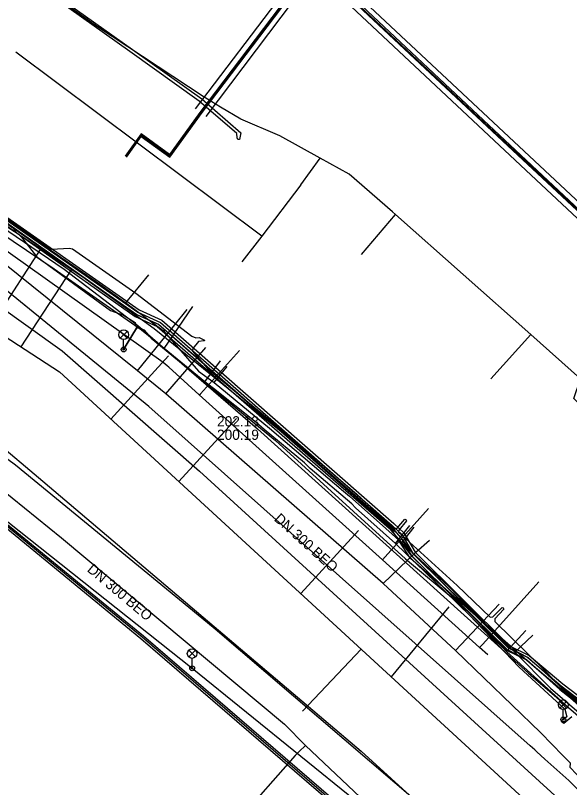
# Model space of a CAD drawing. Extents: x -598932 to -598196, y -1162210 to -1161504.
# Drawn here: x -598866.4 to -598823.1, y -1161758.8 to -1161698.4 of the extents above; entities that cross this region are included whole.
import ezdxf

# ---------------------------------------------------------------- set-up
doc = ezdxf.new("R2010")
doc.units = 0
for name, color, linetype in [('Vrstva 1', 7, 'Continuous'), ('Vrstva 12', 7, 'Continuous'), ('Vrstva 13', 7, 'Continuous'), ('Vrstva 14', 7, 'Continuous'), ('Vrstva 16', 7, 'Continuous'), ('Vrstva 19', 7, 'Continuous'), ('Vrstva 25', 7, 'Continuous'), ('Vrstva 26', 7, 'Continuous'), ('Vrstva 30', 7, 'Continuous'), ('Vrstva 33', 7, 'Continuous'), ('Vrstva 4', 7, 'Continuous'), ('Vrstva 42', 7, 'Continuous'), ('Vrstva 44', 7, 'Continuous'), ('Vrstva 55', 7, 'Continuous'), ('Vrstva 58', 7, 'Continuous'), ('Vrstva 9', 7, 'Continuous')]:
    doc.layers.add(name, color=color, linetype=linetype)

msp = doc.modelspace()

# ---------------------------------------------------------------- linework, layer by layer
at = {"layer": 'Vrstva 1'}
for p, q in [((-598892.23, -1161711.3), (-598864.64, -1161734.54)), ((-598864.64, -1161734.54), (-598839.42, -1161755.92)), ((-598852.066, -1161734.061), (-598815.57, -1161767.334)), ((-598839.42, -1161755.92), (-598800.999, -1161790.997))]:
    msp.add_line(p, q, dxfattribs=at)
msp.add_lwpolyline([(-598893.601, -1161702.614), (-598862.803, -1161724.661), (-598852.066, -1161734.061)], dxfattribs=at)
at = {"layer": 'Vrstva 12'}
for p, q in [((-598857.82, -1161720.91), (-598856.01, -1161718.71)), ((-598850.92, -1161727.13), (-598849.9, -1161725.86)), ((-598836.26, -1161739.64), (-598835.3, -1161738.43)), ((-598827.43, -1161748.2), (-598826.02, -1161746.86))]:
    msp.add_line(p, q, dxfattribs=at)
for points in [[(-598886.1, -1161699.15), (-598877.79, -1161704.85), (-598875.68, -1161706.42), (-598875.36, -1161706.84), (-598872.64, -1161710.75), (-598871.85, -1161711.4), (-598865.87, -1161715.26), (-598859.85, -1161719.44), (-598857.82, -1161720.91)], [(-598857.82, -1161720.91), (-598854.89, -1161723.07), (-598852.13, -1161726.23), (-598850.92, -1161727.13)], [(-598850.92, -1161727.13), (-598846.58, -1161730.68), (-598840.81, -1161735.6), (-598840.34, -1161736.01)], [(-598840.34, -1161736.01), (-598837.51, -1161738.54), (-598836.26, -1161739.64)], [(-598836.26, -1161739.64), (-598832.61, -1161743.04), (-598829.07, -1161746.62), (-598827.43, -1161748.2)], [(-598827.43, -1161748.2), (-598824.64, -1161751), (-598821.47, -1161753.73), (-598817.61, -1161756.73), (-598815.83, -1161758.13), (-598815.16, -1161758.58), (-598814.14, -1161758.66), (-598813.17, -1161758.37), (-598812.14, -1161757.76)]]:
    msp.add_lwpolyline(points, dxfattribs=at)
at = {"layer": 'Vrstva 13'}
for p, q in [((-598860.02, -1161699.34), (-598868.99, -1161692.92)), ((-598851.78, -1161704.78), (-598860.02, -1161699.34)), ((-598847.2, -1161715.68), (-598866.41, -1161701.32)), ((-598850.42, -1161705.6), (-598851.78, -1161704.78)), ((-598848.83, -1161706.56), (-598850.42, -1161705.6)), ((-598845.78, -1161707.85), (-598848.83, -1161706.56)), ((-598842.64, -1161709.6), (-598845.78, -1161707.85)), ((-598844.15, -1161711.69), (-598842.64, -1161709.6)), ((-598844.15, -1161711.69), (-598847.2, -1161715.68)), ((-598839.4, -1161717.11), (-598836.74, -1161714)), ((-598836.74, -1161714), (-598836.97, -1161713.79)), ((-598836.74, -1161714), (-598826.17, -1161723.38)), ((-598847.2, -1161715.68), (-598848.76, -1161717.7)), ((-598829.3, -1161726.84), (-598826.17, -1161723.38))]:
    msp.add_line(p, q, dxfattribs=at)
for points in [[(-598836.97, -1161713.79), (-598840.37, -1161710.85), (-598842.64, -1161709.6)], [(-598821.4, -1161729.73), (-598822.82, -1161728.37), (-598822.28, -1161726.83), (-598826.17, -1161723.38)]]:
    msp.add_lwpolyline(points, dxfattribs=at)
at = {"layer": 'Vrstva 14'}
msp.add_line((-598843.777, -1161755.473), (-598844.27, -1161755.959), dxfattribs=at)
for points in [[(-598829.54, -1161748.41), (-598830.18, -1161747.833), (-598837.775, -1161740.986), (-598852.077, -1161728.091), (-598854.47, -1161725.935), (-598854.596, -1161725.824), (-598854.898, -1161725.553), (-598904.716, -1161690.077), (-598907.876, -1161688.204), (-598922.595, -1161680.155)], [(-598932.017, -1161691.842), (-598923.09, -1161696.61), (-598873.47, -1161730.66), (-598862.84, -1161739.26), (-598845.42, -1161753.81), (-598843.777, -1161755.473), (-598775.893, -1161819.626), (-598773.362, -1161822.181), (-598772.235, -1161823.459), (-598713.72, -1161886.81), (-598709.736, -1161891.092), (-598695.338, -1161905.651)], [(-598852.077, -1161728.091), (-598851.994, -1161727.999), (-598848.947, -1161724.618)], [(-598837.775, -1161740.986), (-598837.555, -1161740.741), (-598834.163, -1161736.979)], [(-598830.18, -1161747.833), (-598829.932, -1161747.558), (-598825.54, -1161742.685)], [(-598844.27, -1161755.959), (-598844.59, -1161756.276), (-598849.04, -1161761.33)]]:
    msp.add_lwpolyline(points, dxfattribs=at)
at = {"layer": 'Vrstva 16'}
for p, q in [((-598854.7, -1161728), (-598851.57, -1161724.4)), ((-598832.06, -1161748.07), (-598828.64, -1161744.44))]:
    msp.add_line(p, q, dxfattribs=at)
for points in [[(-598823.373, -1161756.543), (-598824.813, -1161755.083), (-598825.101, -1161754.79), (-598825.418, -1161754.469), (-598832.06, -1161748.07), (-598837.71, -1161742.83), (-598854.7, -1161728), (-598856.9, -1161726.21), (-598874.5, -1161712.08), (-598882.61, -1161706.08), (-598903.54, -1161692.14), (-598932.017, -1161675.35)], [(-598856.9, -1161726.21), (-598853.99, -1161722.61), (-598853.02, -1161721.42)], [(-598837.71, -1161742.83), (-598835.16, -1161740.39), (-598834.09, -1161739.44)], [(-598813.446, -1161765.959), (-598813.584, -1161766.111), (-598817.151, -1161762.783), (-598817.918, -1161762.107), (-598818.778, -1161761.343), (-598821.353, -1161758.963), (-598821.816, -1161758.537), (-598822.612, -1161757.714), (-598823.092, -1161757.194), (-598823.086, -1161756.852), (-598823.373, -1161756.543)]]:
    msp.add_lwpolyline(points, dxfattribs=at)
at = {"layer": 'Vrstva 19'}
for points in [[(-598825.074, -1161756.558), (-598825.698, -1161755.986), (-598825.873, -1161755.832), (-598826.048, -1161755.671), (-598826.225, -1161755.508), (-598856.03, -1161729), (-598875.4, -1161713.22), (-598905.83, -1161691.44), (-598927.55, -1161680.41), (-598932.017, -1161677.987)], [(-598816.357, -1161764.52), (-598817.643, -1161763.323), (-598818.34, -1161762.707), (-598819.257, -1161761.861), (-598821.847, -1161759.5), (-598822.339, -1161759.067), (-598823.212, -1161758.218), (-598825.074, -1161756.558)]]:
    msp.add_lwpolyline(points, dxfattribs=at)
at = {"layer": 'Vrstva 25'}
for points in [[(-598812.832, -1161722.6), (-598820.563, -1161715.454), (-598826.222, -1161710.177), (-598840.284, -1161696.982), (-598843.04, -1161694.515), (-598845.126, -1161697.003), (-598851.97, -1161706.045)], [(-598851.97, -1161706.045), (-598854.39, -1161709.409), (-598856.623, -1161707.801), (-598857.646, -1161709.221)]]:
    msp.add_lwpolyline(points, dxfattribs=at)
at = {"layer": 'Vrstva 26'}
for points in [[(-598852.369, -1161705.743), (-598845.517, -1161696.691), (-598843.091, -1161693.798), (-598839.946, -1161696.614), (-598825.88, -1161709.811), (-598820.222, -1161715.087), (-598812.841, -1161721.91)], [(-598813.559, -1161722.609), (-598820.903, -1161715.82), (-598826.563, -1161710.542), (-598840.622, -1161697.351), (-598842.988, -1161695.232), (-598844.735, -1161697.314), (-598851.572, -1161706.347)]]:
    msp.add_lwpolyline(points, dxfattribs=at)
at = {"layer": 'Vrstva 30'}
for points in [[(-598777.724, -1161688.444), (-598792.286, -1161702.439), (-598804.464, -1161714.291), (-598812.832, -1161722.483), (-598822.35, -1161713.687), (-598829.465, -1161707.007), (-598840.234, -1161696.86), (-598843.042, -1161694.402), (-598845.193, -1161696.958), (-598852.042, -1161706.02), (-598854.406, -1161709.301), (-598856.63, -1161707.698), (-598857.882, -1161709.43)], [(-598857.777, -1161709.505), (-598856.607, -1161707.909), (-598854.378, -1161709.514), (-598851.866, -1161706.03), (-598845.048, -1161697.037), (-598843.031, -1161694.652), (-598839.702, -1161697.673), (-598827.584, -1161709), (-598812.956, -1161722.622), (-598818.988, -1161728.469), (-598812.053, -1161735.699), (-598820.315, -1161744.584)]]:
    msp.add_lwpolyline(points, dxfattribs=at)
at = {"layer": 'Vrstva 33'}
for p, q in [((-598858.255, -1161723.125), (-598857.725, -1161723.655)), ((-598858.255, -1161723.655), (-598857.725, -1161723.125)), ((-598857.99, -1161724.54), (-598857.99, -1161723.765)), ((-598852.905, -1161748.035), (-598852.375, -1161748.565)), ((-598852.905, -1161748.565), (-598852.375, -1161748.035)), ((-598852.64, -1161749.45), (-598852.64, -1161748.675)), ((-598823.905, -1161752.035), (-598823.375, -1161752.565)), ((-598823.905, -1161752.565), (-598823.375, -1161752.035)), ((-598823.64, -1161753.45), (-598823.64, -1161752.675))]:
    msp.add_line(p, q, dxfattribs=at)
for centre, radius in [((-598857.99, -1161723.39), 0.375), ((-598857.99, -1161724.54), 0.19), ((-598857.99, -1161724.54), 0.05), ((-598852.64, -1161748.3), 0.375), ((-598852.64, -1161749.45), 0.19), ((-598852.64, -1161749.45), 0.05), ((-598823.64, -1161752.3), 0.375), ((-598823.64, -1161753.45), 0.19), ((-598823.64, -1161753.45), 0.05)]:
    msp.add_circle(centre, radius, dxfattribs=at)
at = {"layer": 'Vrstva 42'}
for points in [[(-598932.017, -1161673.922), (-598927.716, -1161676.239), (-598912.291, -1161685.333), (-598913.149, -1161686.963), (-598920.569, -1161699.456), (-598920.751, -1161700.261), (-598910.738, -1161706.755), (-598893.483, -1161718.167), (-598876.589, -1161730.881), (-598867.477, -1161737.872), (-598856.444, -1161746.915), (-598838.797, -1161762.111), (-598820.961, -1161780.547), (-598809.359, -1161793.3), (-598752.857, -1161856.721), (-598745.208, -1161865.511), (-598726.323, -1161886.484), (-598722.413, -1161888.903), (-598722.054, -1161888.564)], [(-598932.017, -1161673.922), (-598927.716, -1161676.239), (-598912.291, -1161685.333), (-598913.149, -1161686.963), (-598920.569, -1161699.456), (-598920.751, -1161700.261), (-598910.738, -1161706.755), (-598893.483, -1161718.167), (-598876.589, -1161730.881), (-598867.477, -1161737.872), (-598856.444, -1161746.915), (-598838.797, -1161762.111), (-598820.961, -1161780.547), (-598809.359, -1161793.3), (-598752.857, -1161856.721), (-598745.208, -1161865.511), (-598726.323, -1161886.484), (-598722.413, -1161888.903), (-598722.053, -1161888.563)], [(-598722.546, -1161888.247), (-598722.93, -1161888.76), (-598726.42, -1161886.6), (-598745.32, -1161865.61), (-598752.97, -1161856.82), (-598791.34, -1161813.75), (-598809.47, -1161793.4), (-598821.07, -1161780.65), (-598838.9, -1161762.22), (-598856.54, -1161747.03), (-598867.57, -1161737.99), (-598876.68, -1161731), (-598893.57, -1161718.29), (-598910.82, -1161706.88), (-598920.92, -1161700.33), (-598920.71, -1161699.4), (-598913.28, -1161686.89), (-598912.49, -1161685.39), (-598927.79, -1161676.37), (-598932.017, -1161674.093)], [(-598722.486, -1161888.162), (-598723.009, -1161888.888), (-598726.517, -1161886.716), (-598745.432, -1161865.709), (-598753.083, -1161856.919), (-598809.581, -1161793.5), (-598821.179, -1161780.753), (-598839.003, -1161762.329), (-598856.636, -1161747.145), (-598867.663, -1161738.108), (-598876.771, -1161731.119), (-598893.657, -1161718.413), (-598910.902, -1161707.005), (-598921.089, -1161700.399), (-598920.851, -1161699.344), (-598913.411, -1161686.817), (-598912.689, -1161685.447), (-598927.864, -1161676.501), (-598932.017, -1161674.264)], [(-598722.486, -1161888.162), (-598723.009, -1161888.888), (-598726.517, -1161886.716), (-598745.432, -1161865.709), (-598753.083, -1161856.919), (-598809.581, -1161793.5), (-598821.179, -1161780.753), (-598839.003, -1161762.329), (-598856.636, -1161747.145), (-598867.663, -1161738.108), (-598876.771, -1161731.119), (-598893.657, -1161718.413), (-598910.902, -1161707.005), (-598921.089, -1161700.399), (-598920.851, -1161699.344), (-598913.411, -1161686.817), (-598912.689, -1161685.447), (-598927.864, -1161676.501), (-598932.017, -1161674.264)], [(-598777.724, -1161688.444), (-598792.286, -1161702.439), (-598804.464, -1161714.291), (-598812.832, -1161722.483), (-598822.35, -1161713.687), (-598829.465, -1161707.007), (-598840.234, -1161696.86), (-598843.042, -1161694.402), (-598845.193, -1161696.958), (-598852.042, -1161706.02), (-598854.406, -1161709.301), (-598856.63, -1161707.698), (-598857.882, -1161709.43)], [(-598867.98, -1161693.46), (-598863.2, -1161696.89), (-598857.29, -1161701.1), (-598851.87, -1161704.95), (-598848.839, -1161707.62), (-598848.925, -1161708.145), (-598849.059, -1161708.141), (-598849.111, -1161708.009), (-598849.136, -1161707.655), (-598852.09, -1161705.14), (-598857.5, -1161701.27), (-598863.26, -1161697.15), (-598863.566, -1161697.668), (-598863.687, -1161697.645), (-598863.75, -1161697.548), (-598863.46, -1161697), (-598868.11, -1161693.62)], [(-598857.777, -1161709.505), (-598856.607, -1161707.909), (-598854.378, -1161709.514), (-598851.866, -1161706.03), (-598845.048, -1161697.037), (-598843.031, -1161694.652), (-598839.702, -1161697.673), (-598827.584, -1161709), (-598812.956, -1161722.622), (-598818.988, -1161728.469), (-598812.053, -1161735.699), (-598820.315, -1161744.584)], [(-598868.28, -1161713.55), (-598863.7, -1161716.69), (-598863.6, -1161716.7), (-598862.25, -1161716.63), (-598861.98, -1161716.67), (-598857.04, -1161720.13), (-598852.65, -1161723.49), (-598852.36, -1161723.62), (-598852.1, -1161723.6), (-598851.667, -1161723.808), (-598851.662, -1161723.85), (-598851.707, -1161723.864), (-598852.14, -1161723.93), (-598852.59, -1161724.47), (-598852.61, -1161724.68), (-598851.44, -1161726.02), (-598845.55, -1161730.91), (-598839.77, -1161735.84), (-598836.82, -1161738.59), (-598836.64, -1161738.54), (-598836.027, -1161737.811), (-598835.931, -1161737.83), (-598835.898, -1161737.922), (-598836.477, -1161738.671), (-598836.52, -1161738.82), (-598831.93, -1161742.99), (-598829.36, -1161745.46), (-598829.137, -1161745.429), (-598828.413, -1161744.708), (-598828.324, -1161744.733), (-598828.283, -1161744.821)], [(-598828.283, -1161744.821), (-598828.986, -1161745.593), (-598828.98, -1161745.79), (-598825.08, -1161749.62), (-598821.61, -1161753.21)]]:
    msp.add_lwpolyline(points, dxfattribs=at)
at = {"layer": 'Vrstva 44'}
for points in [[(-598869.209, -1161713.435), (-598857.08, -1161721.977), (-598855.364, -1161722.745), (-598837.231, -1161738.51), (-598836.388, -1161739.513), (-598835.545, -1161740.616), (-598828.019, -1161747.992), (-598826.507, -1161748.773), (-598823.904, -1161751.097), (-598815.879, -1161757.391), (-598814.668, -1161758.228), (-598813.399, -1161758.744), (-598811.714, -1161758.384), (-598810.069, -1161757.43), (-598798.4, -1161745.861), (-598789.041, -1161736.692), (-598781.817, -1161729.839), (-598780.417, -1161728.178), (-598770.071, -1161718.132)], [(-598869.131, -1161713.245), (-598856.98, -1161721.803), (-598855.256, -1161722.575), (-598837.089, -1161738.37), (-598836.232, -1161739.387), (-598835.395, -1161740.484), (-598827.901, -1161747.828), (-598826.393, -1161748.607), (-598823.776, -1161750.943), (-598815.761, -1161757.229), (-598814.572, -1161758.052), (-598813.381, -1161758.536), (-598811.786, -1161758.196), (-598810.191, -1161757.27), (-598798.54, -1161745.719), (-598789.179, -1161736.548), (-598781.963, -1161729.701), (-598780.563, -1161728.042), (-598770.209, -1161717.988)]]:
    msp.add_lwpolyline(points, dxfattribs=at)
at = {"layer": 'Vrstva 55'}
for points in [[(-598866.59, -1161715.18), (-598865.98, -1161715.76), (-598864.79, -1161717.29), (-598859.01, -1161721.5), (-598858, -1161721.86), (-598857.1, -1161722.43), (-598856.98, -1161722.88), (-598857.99, -1161724.54), (-598856.98, -1161722.88), (-598856.75, -1161722.82), (-598856.4, -1161723.01), (-598855.84, -1161723.65), (-598846.13, -1161731.66), (-598835.97, -1161740.91), (-598832.09, -1161744.14), (-598827.08, -1161749.36), (-598823.51, -1161752.65), (-598823.35, -1161753.24), (-598823.64, -1161753.45), (-598823.79, -1161753.59), (-598823.6, -1161753.73), (-598822.98, -1161753.23)], [(-598885.76, -1161723.17), (-598852.64, -1161749.45), (-598827.15, -1161770.07), (-598815.83, -1161780.75), (-598802.91, -1161792.53), (-598792.55, -1161802.078), (-598793.7, -1161803.05)]]:
    msp.add_lwpolyline(points, dxfattribs=at)
at = {"layer": 'Vrstva 58'}
for p, q in [((-598854.83, -1161724.47), (-598852.589, -1161721.191)), ((-598851.64, -1161727.07), (-598854.83, -1161724.47)), ((-598851.64, -1161727.07), (-598850.42, -1161725.43)), ((-598836.76, -1161739.7), (-598835.62, -1161738.3)), ((-598828.08, -1161748.15), (-598826.56, -1161746.5))]:
    msp.add_line(p, q, dxfattribs=at)
for points in [[(-598854.83, -1161724.47), (-598856.6, -1161723.03), (-598863.41, -1161718.27), (-598873.13, -1161711.72), (-598874.07, -1161710.85), (-598876.83, -1161707.02), (-598890.39, -1161697.57), (-598891.22, -1161696.97), (-598902.04, -1161689.16), (-598904.65, -1161687.39), (-598905.17, -1161686.9), (-598909.13, -1161684.5), (-598922.36, -1161677.33), (-598926.46, -1161675.04), (-598932.017, -1161671.816)], [(-598932.017, -1161673.048), (-598910.041, -1161684.816), (-598901.421, -1161690.062), (-598886.196, -1161700.576), (-598875.501, -1161708.113), (-598873.869, -1161710.176), (-598870.843, -1161712.475), (-598868.959, -1161712.906), (-598868.699, -1161713.121), (-598856.77, -1161721.456), (-598855.01, -1161722.26), (-598836.865, -1161738.142), (-598836.102, -1161738.864), (-598835.201, -1161740.376), (-598827.833, -1161747.695), (-598826.3, -1161748.441), (-598823.685, -1161750.664), (-598815.491, -1161756.899), (-598814.153, -1161757.868)], [(-598932.017, -1161673.501), (-598910.239, -1161685.164), (-598901.639, -1161690.398), (-598886.424, -1161700.904), (-598875.779, -1161708.407), (-598874.151, -1161710.464), (-598871.017, -1161712.845), (-598869.141, -1161713.274), (-598868.941, -1161713.439), (-598856.97, -1161721.804), (-598855.23, -1161722.6), (-598837.135, -1161738.438), (-598836.418, -1161739.116), (-598835.519, -1161740.624), (-598828.067, -1161748.025), (-598826.52, -1161748.779), (-598823.935, -1161750.976), (-598815.729, -1161757.221), (-598814.307, -1161758.252), (-598813.04, -1161758.422), (-598811.744, -1161758.253)], [(-598932.017, -1161673.501), (-598910.239, -1161685.164), (-598901.639, -1161690.398), (-598886.424, -1161700.904), (-598875.779, -1161708.407), (-598874.151, -1161710.464), (-598871.017, -1161712.845), (-598869.141, -1161713.274), (-598868.941, -1161713.439), (-598856.97, -1161721.804), (-598855.23, -1161722.6), (-598837.135, -1161738.438), (-598836.418, -1161739.116), (-598835.519, -1161740.624), (-598828.067, -1161748.025), (-598826.52, -1161748.779), (-598823.935, -1161750.976), (-598815.729, -1161757.221), (-598814.307, -1161758.252), (-598813.04, -1161758.422), (-598811.744, -1161758.253)], [(-598906.92, -1161681.9), (-598906.73, -1161682), (-598908.07, -1161684.68), (-598908.96, -1161686.46), (-598909.66, -1161686.85), (-598910.62, -1161686.81), (-598911.44, -1161686.34), (-598911.54, -1161685.75), (-598911.24, -1161685.48), (-598901.76, -1161690.91), (-598894.88, -1161695.6), (-598889.99, -1161699), (-598882.71, -1161704.32), (-598875.2, -1161709.61), (-598867.61, -1161714.89), (-598862.64, -1161718.26), (-598856.89, -1161722.68), (-598847.53, -1161730.74), (-598826.36, -1161749.84), (-598821.93, -1161753.63), (-598818.09, -1161757.31), (-598817.47, -1161757.65)], [(-598815.57, -1161757.946), (-598816.564, -1161756.821), (-598822.29, -1161752.46), (-598826.7, -1161748.67), (-598835.57, -1161740.87), (-598837.06, -1161738.59), (-598845.42, -1161731.19), (-598855.61, -1161722.93), (-598861.19, -1161718.9), (-598869.25, -1161713.56), (-598871.02, -1161712.63), (-598875.52, -1161708.87), (-598883.3, -1161703.42), (-598891.84, -1161697.55), (-598902.07, -1161690.39), (-598909.96, -1161685.58), (-598910.5, -1161685.33)], [(-598868.82, -1161713.28), (-598856.87, -1161721.63), (-598855.12, -1161722.43), (-598837, -1161738.29), (-598836.26, -1161738.99), (-598835.36, -1161740.5), (-598827.95, -1161747.86), (-598826.41, -1161748.61), (-598823.81, -1161750.82), (-598815.61, -1161757.06), (-598814.23, -1161758.06), (-598813.04, -1161758.22), (-598811.81, -1161758.06), (-598810.37, -1161757.22), (-598798.72, -1161745.6), (-598789.33, -1161736.46), (-598782.19, -1161729.57), (-598780.67, -1161727.93), (-598770.27, -1161717.87)], [(-598836.76, -1161739.7), (-598839.86, -1161736.92), (-598840.16, -1161736.59), (-598843.41, -1161733.84), (-598843.85, -1161733.39), (-598847.02, -1161730.79), (-598847.64, -1161730.25), (-598850.98, -1161727.59), (-598851.64, -1161727.07)], [(-598828.08, -1161748.15), (-598832.03, -1161744.25), (-598836.76, -1161739.7)], [(-598796.22, -1161744.56), (-598797.78, -1161746.1), (-598798.7, -1161746.44), (-598799.28, -1161747.61), (-598809.96, -1161758.43), (-598812.29, -1161760.38), (-598812.94, -1161760.84), (-598813.66, -1161760.66), (-598814.82, -1161759.62), (-598815.73, -1161758.61), (-598820.95, -1161754.6), (-598821.82, -1161753.8), (-598822.41, -1161753.25), (-598828.08, -1161748.15)]]:
    msp.add_lwpolyline(points, dxfattribs=at)
at = {"layer": 'Vrstva 9'}
for p, q in [((-598932.017, -1161681.381), (-598863.01, -1161726.284)), ((-598868.408, -1161722.772), (-598864.482, -1161716.738)), ((-598865.986, -1161724.348), (-598862.06, -1161718.314)), ((-598858.99, -1161729.978), (-598854.484, -1161725.05)), ((-598863.01, -1161726.284), (-598815.194, -1161770.22)), ((-598853.666, -1161734.87), (-598849.158, -1161729.94)), ((-598844.145, -1161743.618), (-598839.633, -1161738.684)), ((-598837.06, -1161750.128), (-598832.55, -1161744.66)), ((-598844.01, -1161752.809), (-598839.425, -1161747.955))]:
    msp.add_line(p, q, dxfattribs=at)
for points in [[(-598913.268, -1161698.946), (-598910.65, -1161700.86), (-598866.44, -1161733.56), (-598852.175, -1161745.288)], [(-598852.175, -1161745.288), (-598850.85, -1161746.38), (-598820.61, -1161772.22), (-598820.296, -1161772.534)]]:
    msp.add_lwpolyline(points, dxfattribs=at)

# ---------------------------------------------------------------- texts
at = {"layer": 'Vrstva 4'}
for s, p in [('202.13', (-598850.693, -1161730.555)), ('200.19', (-598850.693, -1161731.605))]:
    msp.add_text(s, height=0.8, dxfattribs=at).set_placement(p)
for rotation, p in [(318, (-598846.283, -1161737.863)), (320, (-598860.898, -1161741.83))]:
    msp.add_text('DN 300 BEO', height=0.8, rotation=rotation, dxfattribs=at).set_placement(p)

doc.saveas('drawing.dxf')
